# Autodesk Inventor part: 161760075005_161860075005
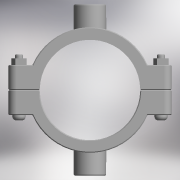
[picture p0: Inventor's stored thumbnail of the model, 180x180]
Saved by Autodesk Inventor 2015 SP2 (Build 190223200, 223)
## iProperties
Created: 2017-05
Part Number: 161760075005_161860075005
Material: Generic
Description: PLASSON DOUBLE SADDLE 75-1/2"
Document SubType Name: Modeling
Designer: KIM
Density: 1 g/cm^3
Appearance: Default
Author: KIM
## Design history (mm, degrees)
derived "16176.ipt"
feature "Solid1::16176.ipt"
feature "Solid2::16176.ipt"
tag "TaggingFeature1"
body "Solid1"
body "Solid2"
other parameters: "d0" = 93.75, "d1" = 122, "d2" = 37.5, "d3" = 75, "d4" = 98, "d5" = 0, "d6" = 6.1, "d7" = 122, "d8" = 0.1, "d10" = 0, "d11" = 0.75, "d20" = 0.75, "d23" = 0.75, "d37" = 8, "d38" = 45.5, "d39" = 0, "d40" = 3, "d41" = 5, "d42" = 0, "d43" = 6, "d44" = 3, "d45" = 0, "d46" = 0.75, "d52" = 18.631, "d53" = 18, "d54" = 0, "d55" = 16, "d57" = 0, "d58" = 81, "d60" = 0, "d63" = 8, "d66" = 82, "d67" = 128, "d68" = 24.2203, "d69" = 18.631, "d70" = 18, "d71" = 0, "d72" = 16, "d74" = 0, "d75" = 0.75, "d_" = 75, "B_" = 16, "G_" = 18.631, "A_" = 64, "L_" = 122, "L_1" = 98, "l_2" = 18
